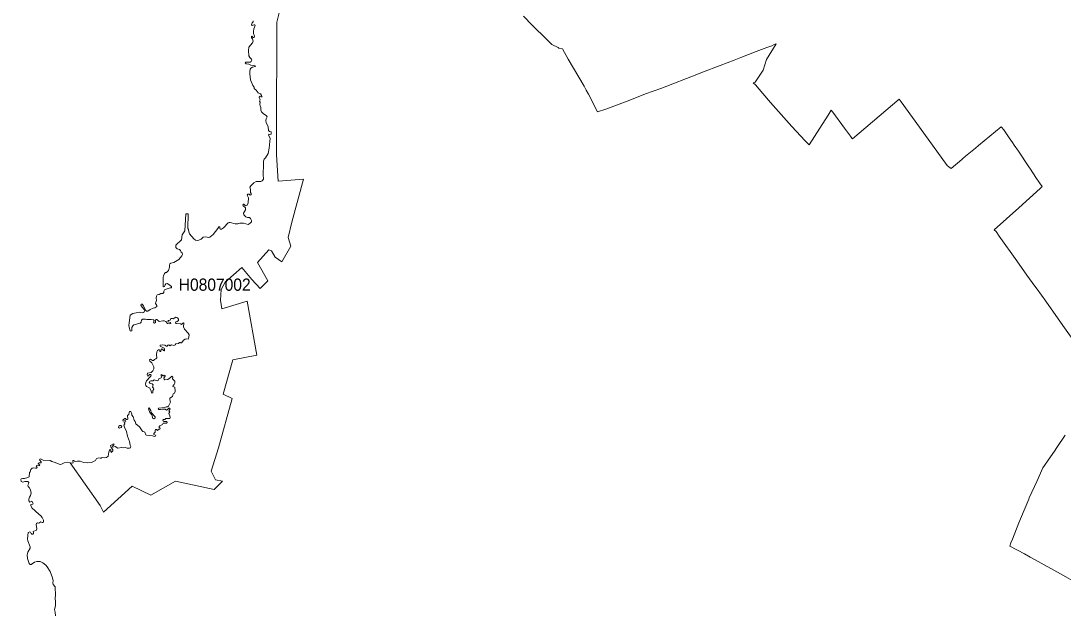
# Model space of a CAD drawing. Extents: x 369010 to 739155, y 6377141 to 6616555.
# Drawn here: x 384068 to 392573, y 6431932 to 6436763 of the extents above; entities that cross this region are included whole.
import ezdxf
from ezdxf.enums import TextEntityAlignment as Align

# ---------------------------------------------------------------- set-up
doc = ezdxf.new("R2010")
doc.units = 0
doc.header["$LTSCALE"] = 40
doc.layers.add('1', color=7, linetype='Continuous', lineweight=13)
doc.layers.add('2', color=7, linetype='Continuous')

msp = doc.modelspace()

# ---------------------------------------------------------------- linework, layer by layer
at = {"layer": '1'}
for points in [[(386142.68, 6434834.52), (386197.63, 6434796.62), (386270.29, 6434924.39), (386248.94, 6434996.06), (386280.22, 6435120.02), (386374.39, 6435472.04), (386166.52, 6435456.16), (386153.94, 6435670.81), (386152.78, 6436102.28), (386156.42, 6436487.58), (386155.26, 6436751.39), (386173.96, 6436817.1), (386193.99, 6436937.91), (386406.33, 6436945.53), (386417.59, 6437033.74), (386377.53, 6437096.96), (386268.8, 6437095.8), (386327.55, 6437227.05), (386538.74, 6437225.72), (386543.87, 6438043.98), (386481.14, 6438071.12), (386428.84, 6438096.44)], [(386173.96, 6436817.1), (386155.26, 6436751.39), (386156.42, 6436487.58), (386152.78, 6436102.28), (386153.94, 6435670.81), (386166.52, 6435456.16), (386374.39, 6435472.04), (386280.22, 6435120.02), (386248.94, 6434996.06), (386270.29, 6434924.39), (386197.63, 6434796.62), (386142.68, 6434834.52), (386111.73, 6434888.48), (386090.22, 6434895.43), (385997.54, 6434793.15), (386083.93, 6434643.53), (386020.05, 6434581.3), (385953.84, 6434654.12), (385870.26, 6434751.44), (385733.89, 6434631.78), (385701.45, 6434570.71), (385696.49, 6434485.14), (385708.4, 6434414.14), (385913.3, 6434477.37), (385993.56, 6434036.13), (385796.62, 6433997.73), (385719.32, 6433718.7), (385790.99, 6433682.95), (385681.59, 6433281.6), (385622.01, 6433089.28), (385656.1, 6433020.43), (385712.54, 6433008.85), (385645.84, 6432939.5), (385328.74, 6433008.85), (385128.48, 6432894.82), (384976.71, 6432968.8), (384740.87, 6432754.63), (384715.87, 6432809.09), (384470.1, 6433159.13), (384445.44, 6433162.93), (384420.78, 6433156.97), (384393.8, 6433145.22), (384380.89, 6433146.05), (384347.96, 6433160.28), (384319.49, 6433168.73), (384307.08, 6433177.33), (384249.98, 6433178.82), (384228.8, 6433190.41), (384221.35, 6433189.25), (384220.19, 6433182.79), (384233.6, 6433165.58), (384233.76, 6433157.8), (384217.04, 6433158.13), (384210.42, 6433152.67), (384221.35, 6433138.6), (384219.2, 6433134.63), (384202.32, 6433138.11), (384192.22, 6433133.14), (384200.16, 6433118.74), (384195.53, 6433114.94), (384186.76, 6433113.61), (384174.01, 6433116.92), (384160.61, 6433114.27), (384149.85, 6433102.36), (384144.39, 6433085.31), (384137.27, 6433080.02), (384136.11, 6433044.27), (384124.36, 6433038.47), (384096.89, 6433031.36), (384083.81, 6433031.36), (384071.57, 6433028.05), (384067.76, 6433021.26), (384071.07, 6433006.53), (384082.99, 6433001.07), (384101.36, 6433005.54), (384124.2, 6433005.7), (384131.98, 6432997.43), (384130.65, 6432986.84), (384125.36, 6432975.25), (384127.51, 6432966.15), (384136.11, 6432957.21), (384147.7, 6432936.52), (384152.83, 6432910.21), (384147.53, 6432890.35), (384138.27, 6432878.93), (384131.81, 6432860.56), (384134.13, 6432848.48), (384140.42, 6432836.89), (384158.46, 6432845.5), (384168.72, 6432826.79), (384165.41, 6432819.68), (384149.52, 6432818.19)], [(385964.6, 6436763.47), (385962.62, 6436756.19), (385954.01, 6436747.75), (385948.71, 6436730.54), (385955.5, 6436725.57), (385971.22, 6436731.53), (385978.34, 6436730.37), (385980.49, 6436724.58), (385968.41, 6436697.6), (385965.43, 6436675.59), (385966.92, 6436659.37), (385975.52, 6436638.85), (385971.39, 6436628.26), (385962.12, 6436626.93), (385953.84, 6436637.69), (385948.71, 6436636.03), (385949.54, 6436623.95), (385957.15, 6436615.51), (385962.12, 6436596.31), (385956.66, 6436583.24), (385929.18, 6436547.99), (385925.54, 6436522.17), (385927.69, 6436477.81), (385935.31, 6436464.74), (385949.04, 6436451), (385951.86, 6436443.39), (385948.05, 6436432.96), (385940.11, 6436427.66), (385904.03, 6436425.68), (385898.57, 6436419.55), (385906.18, 6436412.6), (385927.69, 6436408.96), (385945.24, 6436400.85), (385966.75, 6436400.36), (385977.84, 6436396.88), (385982.97, 6436391.58), (385958.31, 6436385.13), (385943.75, 6436377.52), (385939.61, 6436368.58), (385937.29, 6436350.54), (385936.8, 6436330.35), (385940.93, 6436282.35), (385961.13, 6436237), (385972.21, 6436221.45), (385972.21, 6436210.36), (385989.1, 6436198.94), (386004.16, 6436176.43), (386023.02, 6436168.32), (386032.62, 6436155.25), (386036.26, 6436143.99), (386026.67, 6436143.33), (386016.07, 6436148.13), (386012.1, 6436141.34), (386019.22, 6436119.17), (386015.25, 6436107.91), (386019.71, 6436098.81), (386017.4, 6436080.93), (386019.22, 6436070.51), (386025.51, 6436057.6), (386026.83, 6436034.59), (386031.13, 6436022.01), (386044.04, 6436008.77), (386072.34, 6435989.91), (386076.65, 6435979.81), (386068.7, 6435964.58), (386066.22, 6435949.36)], [(388168.78, 6436800.88), (388240.94, 6436729.05), (388359.44, 6436611.04), (388399.99, 6436570.83), (388453.45, 6436544.68), (388456.76, 6436540.87), (388486.88, 6436534.08), (388534.38, 6436450.17), (388663.81, 6436230.22), (388681.35, 6436198.28), (388699.22, 6436164.18), (388773.87, 6436020.36), (388840.07, 6436044.03), (389036.19, 6436116.85), (389165.45, 6436167.33), (389289.41, 6436212.67), (389597.41, 6436331.67), (389629.52, 6436343.75), (389774.01, 6436399.86), (389888.7, 6436443.22), (389941.66, 6436465.07), (390068.77, 6436513.89), (390155.49, 6436546.5), (390196.54, 6436560.73), (390215.08, 6436570.83), (390232.29, 6436575.13), (390151.03, 6436448.68), (390124.54, 6436360.14), (390059.34, 6436263.98), (390044.61, 6436257.69), (390064.8, 6436237.5), (390076.55, 6436224.92), (390183.96, 6436097.15), (390357.74, 6435902.85), (390467.63, 6435785.84), (390499.58, 6435751.42), (390588.12, 6435888.45), (390653.99, 6435994.71), (390680.8, 6436035.09), (390694.04, 6436018.54), (390789.04, 6435886.96), (390836.71, 6435821.59), (390848.29, 6435805.87), (390852.6, 6435799.91), (391233.26, 6436124.79), (391252.12, 6436101.95), (391436, 6435846.75), (391627.49, 6435582.77)], [(391745.33, 6435631.92), (391658.6, 6435559.93), (391640.89, 6435572.17), (391627.49, 6435582.77), (391436, 6435846.75), (391252.12, 6436101.95), (391233.26, 6436124.79), (390852.6, 6435799.91), (390848.29, 6435805.87), (390836.71, 6435821.59), (390789.04, 6435886.96), (390694.04, 6436018.54), (390680.8, 6436035.09), (390653.99, 6435994.71), (390588.12, 6435888.45), (390499.58, 6435751.42), (390467.63, 6435785.84), (390357.74, 6435902.85), (390183.96, 6436097.15), (390076.55, 6436224.92), (390064.8, 6436237.5), (390044.61, 6436257.69), (390059.34, 6436263.98), (390124.54, 6436360.14), (390151.03, 6436448.68), (390232.29, 6436575.13), (390215.08, 6436570.83), (390196.54, 6436560.73), (390155.49, 6436546.5), (390068.77, 6436513.89), (389941.66, 6436465.07), (389888.7, 6436443.22), (389774.01, 6436399.86), (389629.52, 6436343.75), (389597.41, 6436331.67), (389289.41, 6436212.67), (389165.45, 6436167.33), (389036.19, 6436116.85), (388840.07, 6436044.03), (388773.87, 6436020.36), (388699.22, 6436164.18), (388681.35, 6436198.28), (388663.81, 6436230.22), (388534.38, 6436450.17), (388486.88, 6436534.08), (388456.76, 6436540.87), (388453.45, 6436544.68), (388399.99, 6436570.83), (388359.44, 6436611.04), (388240.94, 6436729.05), (388168.78, 6436800.88)], [(386066.22, 6435949.36), (386070.19, 6435934.3), (386086.91, 6435897.72), (386089.72, 6435868.1), (386095.85, 6435859.49), (386109.75, 6435857.17), (386109.25, 6435838.97), (386099.82, 6435836.32), (386090.38, 6435838.64), (386089.39, 6435830.86), (386103.13, 6435807.36), (386093.69, 6435726.09), (386086.08, 6435681.9), (386064.4, 6435645.82), (386054.3, 6435635.4), (386047.68, 6435618.68), (386046.53, 6435585.41), (386047.85, 6435560.59), (386044.87, 6435540.07), (386044.87, 6435496.87), (386048.18, 6435484.29), (386047.35, 6435470.72), (386037.59, 6435458.47), (386025.18, 6435453.34), (385989.1, 6435451.69), (385968.08, 6435442.09), (385945.9, 6435420.08), (385936.63, 6435405.51), (385941.6, 6435386.48), (385940.6, 6435363.64), (385945.9, 6435356.36), (385947.55, 6435344.61), (385939.78, 6435340.3), (385929.68, 6435349.08), (385918.92, 6435350.73), (385915.28, 6435342.12), (385918.92, 6435330.21), (385926.04, 6435319.45), (385922.56, 6435279.07), (385913.63, 6435260.2), (385904.52, 6435254.74), (385897.41, 6435257.22), (385888.14, 6435267.81), (385880.53, 6435269.3), (385879.2, 6435262.85), (385882.84, 6435255.23), (385900.55, 6435237.03), (385900.06, 6435222.46), (385885.16, 6435195.32), (385887.31, 6435182.08), (385903.86, 6435166.03), (385917.43, 6435160.07), (385933.49, 6435159.41), (385942.76, 6435150.64), (385948.55, 6435134.25), (385949.04, 6435124.49), (385938.95, 6435111.91), (385921.74, 6435102.97), (385885.66, 6435112.07), (385855.87, 6435112.9), (385839.15, 6435108.1), (385815.48, 6435106.94), (385775.27, 6435119.36), (385766.99, 6435118.53), (385758.22, 6435115.38), (385721.15, 6435074.34), (385704.59, 6435063.91), (385694.33, 6435063.91), (385690.53, 6435068.38), (385690.36, 6435082.28), (385683.58, 6435082.78), (385676.46, 6435070.37), (385637.57, 6435021.71), (385610.59, 6434998.37), (385601.98, 6434995.56), (385574.01, 6435001.19), (385556.14, 6434998.21), (385537.93, 6434982.15), (385521.38, 6434974.54), (385506.32, 6434971.89), (385492.92, 6434975.37), (385479.67, 6434984.3), (385444.92, 6435024.85), (385438.8, 6435041.9), (385436.15, 6435061.26), (385429.03, 6435069.37), (385433.5, 6435187.87), (385414.14, 6435189.03), (385407.02, 6435051.83), (385384.34, 6435016.58), (385377.56, 6434977.35), (385333.7, 6434933), (385333.2, 6434914.96), (385342.31, 6434904.03), (385362.99, 6434897.75), (385371.1, 6434888.97), (385375.9, 6434875.9), (385384.51, 6434870.27), (385387.49, 6434857.86), (385382.69, 6434846.44)], [(391627.49, 6435582.77), (391640.89, 6435572.17), (391658.6, 6435559.93), (391745.33, 6435631.92), (391746.81, 6435633.08), (391750.62, 6435636.72), (391776.77, 6435658.73), (391858.53, 6435725.6), (391882.86, 6435747.44), (392067.73, 6435899.71), (392070.04, 6435896.73), (392087.42, 6435874.22), (392131.45, 6435809.67), (392158.09, 6435770.12), (392172.66, 6435749.76), (392207.41, 6435700.44), (392293.64, 6435571.68), (392305.39, 6435552.31), (392349.25, 6435486.77), (392379.04, 6435441.76), (392400.39, 6435410.97), (392399.07, 6435409.48), (392384.34, 6435395.09), (392209.73, 6435239.35), (392010.46, 6435059.77), (392024.7, 6435043.89), (392051.01, 6435006.65), (392193.51, 6434806.88), (392276.92, 6434690.04), (392340.31, 6434599.18), (392359.51, 6434574.52), (392432.17, 6434475.54), (392571.02, 6434277.27), (392890.45, 6433830.08)], [(392890.45, 6433830.08), (392571.02, 6434277.27), (392432.17, 6434475.54), (392359.51, 6434574.52), (392340.31, 6434599.18), (392276.92, 6434690.04), (392193.51, 6434806.88), (392051.01, 6435006.65), (392024.7, 6435043.89), (392010.46, 6435059.77), (392209.73, 6435239.35), (392384.34, 6435395.09), (392399.07, 6435409.48), (392400.39, 6435410.97), (392379.04, 6435441.76), (392349.25, 6435486.77), (392305.39, 6435552.31), (392293.64, 6435571.68), (392207.41, 6435700.44), (392172.66, 6435749.76), (392158.09, 6435770.12), (392131.45, 6435809.67), (392087.42, 6435874.22), (392070.04, 6435896.73), (392067.73, 6435899.71), (391882.86, 6435747.44), (391858.53, 6435725.6), (391776.77, 6435658.73), (391750.62, 6435636.72), (391746.81, 6435633.08), (391745.33, 6435631.92)], [(384973.73, 6433554.35), (384965.79, 6433575.37), (384960.16, 6433576.36), (384955.03, 6433575.37), (384951.88, 6433567.92), (384950.06, 6433552.03), (384938.97, 6433543.1), (384939.8, 6433514.63), (384934.5, 6433511.32), (384928.38, 6433511.32), (384922.09, 6433518.77), (384916.63, 6433519.26), (384904.88, 6433512.81), (384900.41, 6433504.7), (384902.23, 6433498.74), (384921.1, 6433502.55), (384924.41, 6433498.24), (384922.26, 6433493.28), (384912, 6433488.48), (384914.98, 6433475.57), (384907.36, 6433465.64), (384912.99, 6433449.25), (384930.86, 6433412.68), (384936.82, 6433375.61), (384954.86, 6433333.07), (384958.67, 6433303.45), (384963.96, 6433290.54), (384962.31, 6433281.27), (384955.36, 6433276.97), (384935, 6433278.62), (384919.94, 6433283.09), (384904.88, 6433279.12), (384888.49, 6433283.42), (384858.04, 6433276.47), (384837.52, 6433291.69), (384819.15, 6433286.56), (384814.35, 6433293.68), (384827.42, 6433304.44), (384828.42, 6433309.9), (384822.46, 6433312.55), (384800.28, 6433298.48), (384801.27, 6433289.54), (384817.16, 6433265.21), (384818.16, 6433254.79), (384805.74, 6433242.54), (384802.43, 6433247.84), (384802.1, 6433264.55), (384795.81, 6433266.04), (384791.01, 6433261.9), (384784.72, 6433244.69), (384779.76, 6433212.25), (384766.85, 6433202.65), (384751.46, 6433197.85), (384731.27, 6433201.5), (384723.32, 6433195.54), (384715.05, 6433195.87), (384702.8, 6433199.51), (384686.25, 6433193.39), (384676.98, 6433177.5), (384661.26, 6433168.06), (384645.37, 6433161.77), (384613.59, 6433157.97), (384580.16, 6433161.77), (384551.03, 6433170.88), (384530.01, 6433172.53), (384515.45, 6433169.39), (384505.68, 6433171.87), (384498.07, 6433177.99), (384492.28, 6433177.33), (384491.12, 6433172.04), (384495.59, 6433161.94), (384492.28, 6433155.65), (384470.1, 6433159.13), (384715.87, 6432809.09), (384740.87, 6432754.63), (384976.71, 6432968.8), (385128.48, 6432894.82), (385328.74, 6433008.85), (385645.84, 6432939.5), (385712.54, 6433008.85), (385656.1, 6433020.43), (385622.01, 6433089.28), (385681.59, 6433281.6), (385790.99, 6433682.95), (385719.32, 6433718.7), (385796.62, 6433997.73), (385993.56, 6434036.13), (385913.3, 6434477.37), (385708.4, 6434414.14), (385696.49, 6434485.14), (385701.45, 6434570.71), (385733.89, 6434631.78), (385870.26, 6434751.44), (385953.84, 6434654.12), (386020.05, 6434581.3), (386083.93, 6434643.53), (385997.54, 6434793.15), (386090.22, 6434895.43), (386111.73, 6434888.48), (386142.68, 6434834.52)], [(385382.69, 6434846.44), (385358.2, 6434816.32), (385316.65, 6434790.83), (385292.32, 6434786.86), (385284.05, 6434781.4), (385280.9, 6434771.14), (385281.07, 6434755.08), (385271.31, 6434726.95), (385256.74, 6434711.88), (385249.29, 6434710.73), (385240.19, 6434701.46), (385230.76, 6434683.25), (385228.77, 6434673.65), (385230.26, 6434641.88), (385227.78, 6434594.87), (385233.07, 6434592.89), (385240.19, 6434596.03), (385244.49, 6434610.6), (385249.62, 6434619.04), (385261.21, 6434620.36), (385275.77, 6434613.91), (385297.62, 6434597.02), (385297.29, 6434586.43), (385285.21, 6434585.11), (385262.53, 6434576.01), (385241.18, 6434569.22), (385233.57, 6434558.13), (385233.74, 6434547.54), (385226.62, 6434537.94), (385210.23, 6434538.93), (385197.33, 6434530.16), (385179.62, 6434528.84), (385173.66, 6434518.41), (385171.67, 6434503.18), (385175.81, 6434481.83), (385169.02, 6434467.93), (385167.2, 6434457.17), (385177.63, 6434441.78), (385176.64, 6434434.5), (385161.74, 6434423.25), (385148.34, 6434420.43), (385123.01, 6434409.67), (385102.66, 6434394.61), (385094.05, 6434394.94), (385085.78, 6434402.72), (385069.23, 6434439.63), (385057.81, 6434451.05), (385048.21, 6434451.22), (385047.71, 6434445.09), (385056.98, 6434428.05), (385073.03, 6434407.52), (385076.18, 6434398.25), (385071.54, 6434385.01), (385058.96, 6434382.7), (385036.29, 6434386.5), (384982.5, 6434375.25), (384960.32, 6434362.34), (384956.19, 6434342.15), (384948.57, 6434275.62), (384960.32, 6434233.91), (384965.62, 6434231.76), (384972.24, 6434234.57), (384972.07, 6434262.54), (384980.68, 6434275.95), (384990.94, 6434282.57), (385041.75, 6434297.63), (385048.37, 6434305.08), (385051.85, 6434321.13), (385059.46, 6434330.56), (385085.78, 6434331.06), (385096.86, 6434326.09), (385130.46, 6434327.92), (385150.98, 6434325.1), (385154.79, 6434319.14), (385151.48, 6434300.28), (385159.09, 6434298.12), (385166.04, 6434303.92), (385166.87, 6434320.14), (385170.51, 6434326.09), (385178.62, 6434326.26), (385195.67, 6434312.03), (385225.63, 6434317.49), (385236.22, 6434316.33), (385249.79, 6434310.04), (385265.51, 6434295.81), (385283.06, 6434292.66), (385292.16, 6434295.48), (385289.68, 6434304.08), (385268.99, 6434307.89), (385267.66, 6434313.85), (385272.96, 6434319.14), (385286.53, 6434322.95), (385290.67, 6434334.7), (385304.08, 6434335.2), (385310.2, 6434332.55), (385331.55, 6434345.62), (385339.33, 6434344.63), (385349.42, 6434338.51), (385355.38, 6434328.91), (385353.89, 6434320.14)], [(385353.89, 6434320.14), (385344.46, 6434310.04), (385332.21, 6434306.9), (385330.39, 6434300.44), (385334.36, 6434294.32), (385369.45, 6434292.33), (385377.89, 6434285.71), (385388.65, 6434298.62), (385394.11, 6434300.44), (385397.92, 6434296.64), (385394.11, 6434267.84), (385402.22, 6434249.63), (385432.84, 6434215.7), (385440.62, 6434201.8), (385438.96, 6434183.43), (385432.51, 6434166.71), (385419.43, 6434168.2), (385409.67, 6434166.55), (385393.61, 6434158.6), (385382.36, 6434139.9), (385372.92, 6434133.94), (385370.28, 6434140.73), (385361.84, 6434140.73), (385354.72, 6434131.13), (385333.7, 6434128.98), (385327.74, 6434119.38), (385314.83, 6434115.74), (385297.12, 6434120.37), (385284.38, 6434113.59), (385276.27, 6434120.37), (385267, 6434118.72), (385261.71, 6434110.61), (385255.09, 6434110.11), (385242.01, 6434118.39), (385227.45, 6434120.87), (385204.44, 6434118.22), (385205.6, 6434110.11), (385237.38, 6434093.07), (385240.19, 6434085.45), (385239.86, 6434074.53), (385236.72, 6434071.38), (385230.92, 6434073.54), (385226.95, 6434083.3), (385218.51, 6434088.76), (385212.88, 6434081.48), (385210.9, 6434069.23), (385206.76, 6434065.43), (385202.79, 6434065.43), (385202.12, 6434074.03), (385198.48, 6434078.83), (385190.54, 6434078.5), (385181.93, 6434073.37), (385176.47, 6434062.28), (385175.31, 6434038.61), (385176.47, 6434015.28), (385169.85, 6434005.02), (385159.26, 6434001.87), (385149.49, 6433992.6), (385142.54, 6433992.6), (385126.99, 6434003.36), (385117.72, 6433997.57), (385120.2, 6433987.31), (385137.08, 6433972.74), (385153.3, 6433939.97), (385153.63, 6433923.92), (385144.53, 6433908.69), (385129.97, 6433895.29), (385100.51, 6433889.5), (385099.84, 6433874.77), (385105.14, 6433866.16), (385110.6, 6433868.31), (385117.72, 6433877.91), (385125.66, 6433877.91), (385129.97, 6433871.95), (385128.48, 6433864.01), (385119.37, 6433855.57), (385093.39, 6433825.94), (385087.1, 6433813.03), (385085.78, 6433799.79), (385087.1, 6433788.21), (385093.55, 6433781.26), (385116.56, 6433768.84), (385127.48, 6433751.3), (385137.08, 6433727.14), (385143.54, 6433727.96), (385144.69, 6433733.76), (385145.19, 6433747.33), (385153.3, 6433758.91), (385151.48, 6433766.69), (385141.88, 6433775.3), (385146.18, 6433794.99), (385138.57, 6433802.77), (385128.97, 6433804.26), (385121.03, 6433808.4), (385115.73, 6433815.52), (385117.06, 6433821.97), (385129.63, 6433828.09), (385146.85, 6433825.78), (385155.95, 6433836.04), (385181.93, 6433825.78)], [(385181.93, 6433825.78), (385188.88, 6433829.75), (385193.52, 6433843.49), (385214.04, 6433850.11), (385216.69, 6433858.71), (385211.89, 6433867.15), (385213.21, 6433878.08), (385218.84, 6433876.59), (385227.61, 6433868.97), (385232.41, 6433868.97), (385237.87, 6433873.77), (385245.49, 6433870.63), (385246.15, 6433863.68), (385235.23, 6433849.94), (385237.38, 6433841.83), (385243.17, 6433835.87), (385267.5, 6433838.19), (385289.68, 6433853.91), (385299.94, 6433865.17), (385306.89, 6433856.89), (385305.73, 6433842), (385322.94, 6433824.62), (385325.09, 6433807.57), (385318.14, 6433795.65), (385311.03, 6433789.7), (385307.88, 6433781.75), (385323.44, 6433774.47), (385327.91, 6433740.71), (385321.45, 6433727.14), (385310.7, 6433719.69), (385306.39, 6433699.83), (385283.22, 6433685.1), (385282.73, 6433671.03), (385287.86, 6433652.99), (385283.22, 6433642.73), (385272.79, 6433619.89), (385264.35, 6433615.09), (385254.59, 6433615.09), (385243.17, 6433609.79), (385190.04, 6433603.67), (385188.72, 6433598.37), (385194.18, 6433593.24), (385207.26, 6433593.24), (385221.65, 6433596.22), (385245.98, 6433596.22), (385255.75, 6433588.94), (385262.04, 6433589.44), (385275.11, 6433603.34), (385282.73, 6433603.17), (385285.21, 6433597.38), (385276.6, 6433582.49), (385282.23, 6433574.38), (385275.77, 6433559.15), (385282.56, 6433540.94), (385287.36, 6433527.87), (385282.73, 6433519.92), (385273.62, 6433518.6), (385265.51, 6433520.92), (385250.45, 6433520.92), (385243.67, 6433511.65), (385231.25, 6433511.15), (385225.13, 6433506.35), (385228.11, 6433497.91), (385235.23, 6433494.44), (385258.89, 6433495.6), (385260.55, 6433487.65), (385255.75, 6433482.69), (385228.11, 6433482.69), (385224.47, 6433470.27), (385200.64, 6433460.67), (385196, 6433454.05), (385197.33, 6433447.1), (385204.44, 6433440.15), (385202.95, 6433433.2), (385190.37, 6433433.2), (385187.89, 6433426.08), (385183.42, 6433422.94), (385173.66, 6433430.06), (385165.22, 6433429.23), (385163.4, 6433422.94), (385164.22, 6433408.38), (385152.31, 6433396.96), (385152.31, 6433390.17), (385166.21, 6433384.05), (385168.2, 6433378.92), (385157.11, 6433372.96), (385143.21, 6433377.26), (385093.55, 6433382.56), (385087.6, 6433387.36), (385080.48, 6433407.22), (385075.02, 6433411.52), (385064.26, 6433412.68), (385056.81, 6433418.14), (385036.46, 6433452.4), (385005.18, 6433476.4), (384999.88, 6433494.93), (384992.6, 6433504.7), (384983.49, 6433532.17), (384974.39, 6433545.74), (384973.73, 6433554.35)], [(392588.57, 6433383.72), (392520.38, 6433282.43), (392500.69, 6433254.46), (392450.7, 6433178.82), (392419.26, 6433135.29), (392407.18, 6433117.75), (392357.36, 6433005.87), (392337.5, 6432965.65), (392295.46, 6432872.14), (392291.32, 6432861.55), (392255.41, 6432770.85), (392212.21, 6432669.4), (392159.25, 6432536.33), (392145.35, 6432505.22), (392136.25, 6432479.4), (392257.06, 6432415.35), (392303.74, 6432389.37), (392339.15, 6432370.5), (392551.16, 6432251.5), (392694.49, 6432169.91)], [(392694.49, 6432169.91), (392551.16, 6432251.5), (392339.15, 6432370.5), (392303.74, 6432389.37), (392257.06, 6432415.35), (392136.25, 6432479.4), (392145.35, 6432505.22), (392159.25, 6432536.33), (392212.21, 6432669.4), (392255.41, 6432770.85), (392291.32, 6432861.55), (392295.46, 6432872.14), (392337.5, 6432965.65), (392357.36, 6433005.87), (392407.18, 6433117.75), (392419.26, 6433135.29), (392450.7, 6433178.82), (392500.69, 6433254.46), (392520.38, 6433282.43), (392588.57, 6433383.72)], [(384149.52, 6432818.19), (384148.2, 6432810.24), (384158.13, 6432791.38), (384214.4, 6432737.92), (384231.94, 6432724.84), (384242.37, 6432711.44), (384251.97, 6432690.92), (384252.96, 6432677.51), (384248.82, 6432672.21), (384242.7, 6432670.72), (384231.11, 6432675.85), (384213.24, 6432666.75), (384204.14, 6432667.41), (384196.52, 6432663.11), (384192.38, 6432654.5), (384198.01, 6432619.91), (384193.71, 6432604.85), (384172.86, 6432600.22), (384168.39, 6432596.74), (384169.71, 6432590.95), (384172.19, 6432582.34), (384165.74, 6432575.39), (384157.63, 6432575.39), (384152.33, 6432580.19), (384146.04, 6432591.61), (384140.42, 6432594.26), (384128.17, 6432590.29), (384122.54, 6432537.49), (384126.02, 6432521.44), (384144.72, 6432473.11), (384143.89, 6432462.69), (384126.02, 6432430.41), (384119.07, 6432406.25), (384121.71, 6432378.94), (384136.11, 6432336.74), (384143.89, 6432329.79), (384152.17, 6432329.62), (384179.81, 6432347.16), (384199.34, 6432353.95), (384224.66, 6432353.62), (384246.01, 6432343.36), (384270.67, 6432323.33), (384282.25, 6432309.26), (384306.25, 6432271.69), (384326.11, 6432220.88), (384332.07, 6432196.72), (384328.43, 6432178.02), (384330.75, 6432166.43), (384347.96, 6432146.24), (384351.1, 6432076.73), (384346.63, 6432056.04), (384350.94, 6432022.61), (384351.1, 6431991), (384342.5, 6431960.88), (384347.3, 6431940.52), (384351.1, 6431910.07)]]:
    msp.add_lwpolyline(points, dxfattribs=at)
for points in [[(385153.3, 6433518.1), (385163.07, 6433526.21), (385164.06, 6433534.32), (385132.28, 6433567.76), (385127.32, 6433586.13), (385113.58, 6433605.49), (385109.61, 6433598.54), (385119.37, 6433568.42), (385137.25, 6433548.39), (385143.54, 6433519.43)], [(384874.26, 6433462.66), (384866.48, 6433456.37), (384865.49, 6433446.11), (384871.94, 6433440.65), (384886.01, 6433445.94), (384890.98, 6433453.23), (384884.36, 6433462.16)]]:
    msp.add_lwpolyline(points, close=True, dxfattribs=at)

# ---------------------------------------------------------------- texts
at = {"layer": '2', "width": 0.95}
msp.add_text('H0807002', height=100, dxfattribs=at).set_placement((385649.51, 6434561.48), align=Align.CENTER)

doc.saveas('drawing.dxf')
